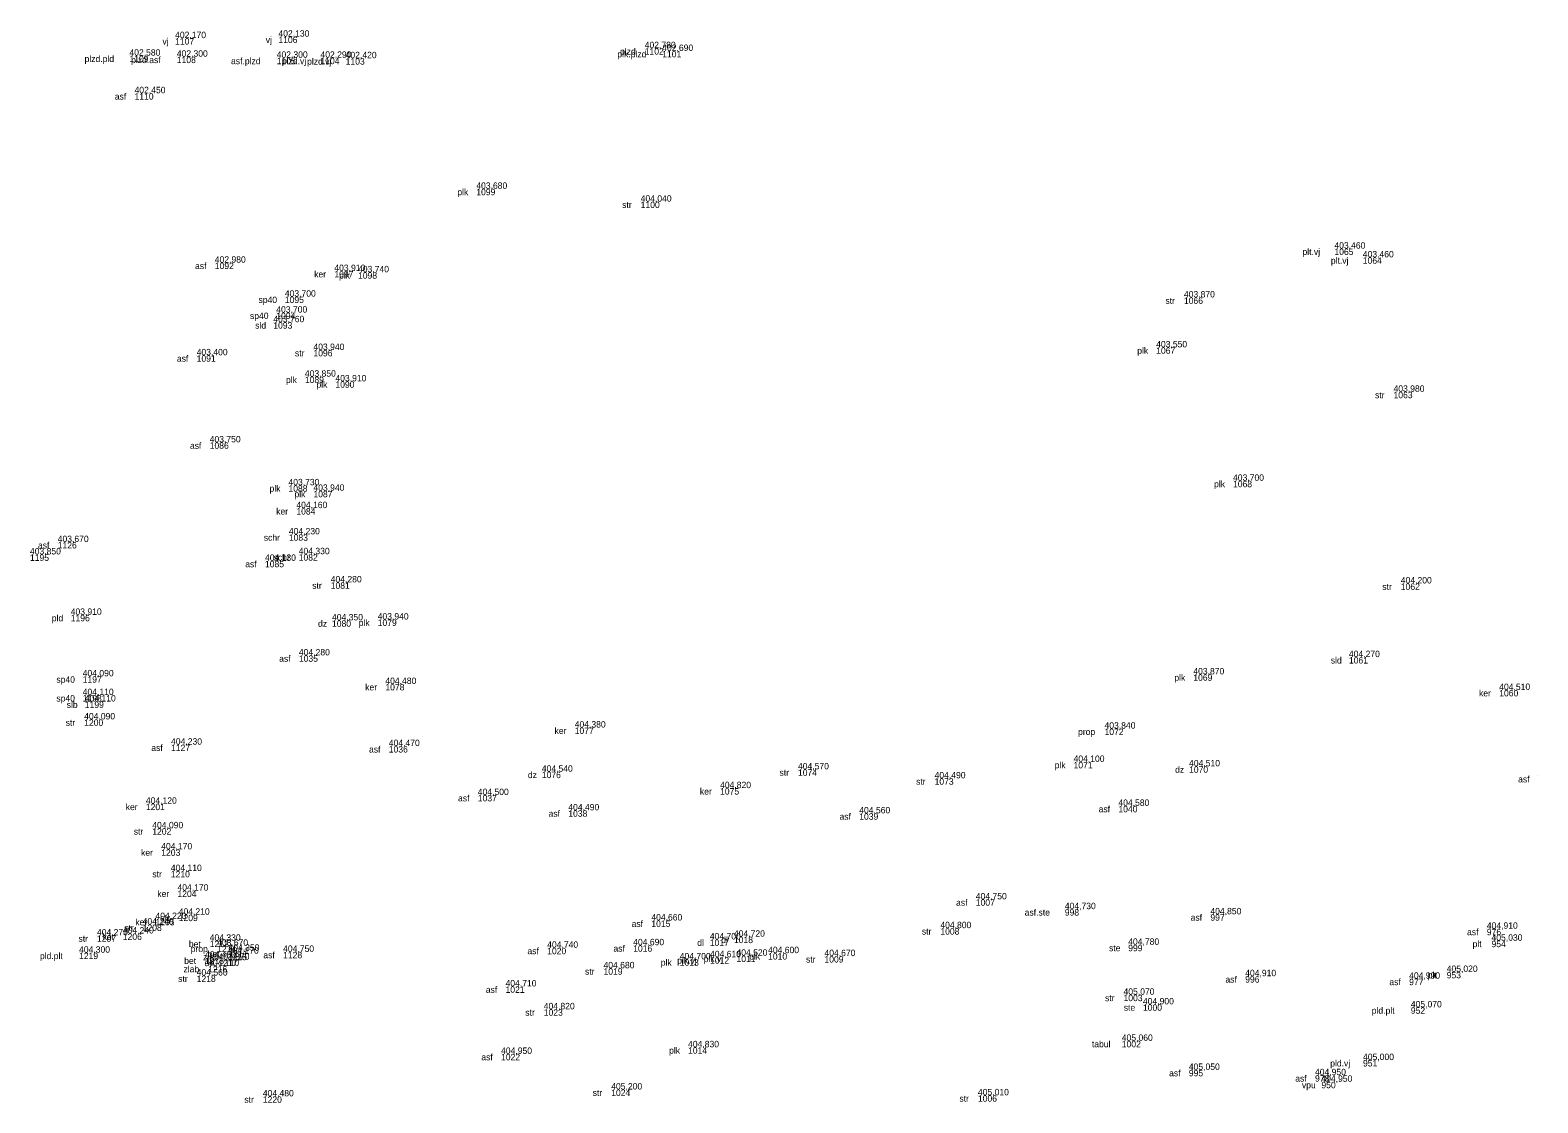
# Model space of a CAD drawing. Extents: x -747136 to -746138, y -1093274 to -1091717.
# Drawn here: x -747043 to -746972.4, y -1092170.4 to -1092120.2 of the extents above; entities that cross this region are included whole.
import ezdxf

# ---------------------------------------------------------------- set-up
doc = ezdxf.new("R2010")
doc.units = 0
for name, color, linetype in [('1029', 7, 'Continuous'), ('404', 7, 'Continuous'), ('424', 7, 'Continuous')]:
    doc.layers.add(name, color=color, linetype=linetype)

msp = doc.modelspace()

# ---------------------------------------------------------------- linework, layer by layer
at = {"layer": '404'}
for p, q in [((-747036.23, -1092120.54), (-747036.23, -1092120.54)), ((-747031.39, -1092120.47), (-747031.39, -1092120.47)), ((-747038.37, -1092121.36), (-747038.37, -1092121.36)), ((-747036.15, -1092121.41), (-747036.15, -1092121.41)), ((-747031.47, -1092121.46), (-747031.47, -1092121.46)), ((-747029.42, -1092121.46), (-747029.42, -1092121.46)), ((-747028.24, -1092121.48), (-747028.24, -1092121.48)), ((-747014.23, -1092121.01), (-747014.23, -1092121.01)), ((-747013.41, -1092121.14), (-747013.41, -1092121.14)), ((-747038.13, -1092123.12), (-747038.13, -1092123.12)), ((-747022.12, -1092127.6), (-747022.12, -1092127.6)), ((-747014.42, -1092128.2), (-747014.42, -1092128.2)), ((-746981.92, -1092130.4), (-746981.92, -1092130.4)), ((-747034.37, -1092131.06), (-747034.37, -1092131.06)), ((-747028.77, -1092131.45), (-747028.77, -1092131.45)), ((-746980.59, -1092130.81), (-746980.59, -1092130.81)), ((-747027.66, -1092131.51), (-747027.66, -1092131.51)), ((-747031.09, -1092132.65), (-747031.09, -1092132.65)), ((-746988.97, -1092132.69), (-746988.97, -1092132.69)), ((-747031.49, -1092133.4), (-747031.49, -1092133.4)), ((-747031.63, -1092133.85), (-747031.63, -1092133.85)), ((-747035.22, -1092135.4), (-747035.22, -1092135.4)), ((-747029.75, -1092135.15), (-747029.75, -1092135.15)), ((-746990.27, -1092135.03), (-746990.27, -1092135.03)), ((-747030.15, -1092136.4), (-747030.15, -1092136.4)), ((-747028.72, -1092136.62), (-747028.72, -1092136.62)), ((-746979.15, -1092137.11), (-746979.15, -1092137.11)), ((-747034.61, -1092139.48), (-747034.61, -1092139.48)), ((-746986.67, -1092141.28), (-746986.67, -1092141.28)), ((-747030.92, -1092141.49), (-747030.92, -1092141.49)), ((-747029.75, -1092141.75), (-747029.75, -1092141.75)), ((-747030.55, -1092142.56), (-747030.55, -1092142.56)), ((-747041.73, -1092144.15), (-747041.73, -1092144.15)), ((-747030.9, -1092143.79), (-747030.9, -1092143.79)), ((-747030.44, -1092144.72), (-747030.44, -1092144.72)), ((-747032.02, -1092145.03), (-747032.02, -1092145.03)), ((-747028.94, -1092146.04), (-747028.94, -1092146.04)), ((-746978.81, -1092146.09), (-746978.81, -1092146.09)), ((-747041.12, -1092147.56), (-747041.12, -1092147.56)), ((-747028.88, -1092147.82), (-747028.88, -1092147.82)), ((-747026.74, -1092147.78), (-747026.74, -1092147.78)), ((-747030.43, -1092149.46), (-747030.43, -1092149.46)), ((-746981.24, -1092149.54), (-746981.24, -1092149.54)), ((-747040.56, -1092150.44), (-747040.56, -1092150.44)), ((-746988.53, -1092150.35), (-746988.53, -1092150.35)), ((-747026.38, -1092150.8), (-747026.38, -1092150.8)), ((-746974.2, -1092151.08), (-746974.2, -1092151.08)), ((-747040.56, -1092151.32), (-747040.56, -1092151.32)), ((-747040.46, -1092151.62), (-747040.46, -1092151.62)), ((-747040.49, -1092152.46), (-747040.49, -1092152.46)), ((-747017.51, -1092152.84), (-747017.51, -1092152.84)), ((-746992.69, -1092152.89), (-746992.69, -1092152.89)), ((-747036.42, -1092153.64), (-747036.42, -1092153.64)), ((-747026.22, -1092153.71), (-747026.22, -1092153.71)), ((-746994.14, -1092154.45), (-746994.14, -1092154.45)), ((-746988.73, -1092154.66), (-746988.73, -1092154.66)), ((-747019.05, -1092154.91), (-747019.05, -1092154.91)), ((-747007.05, -1092154.8), (-747007.05, -1092154.8)), ((-747000.65, -1092155.22), (-747000.65, -1092155.22)), ((-746972.39, -1092155.11), (-746972.39, -1092155.11)), ((-747022.05, -1092156), (-747022.05, -1092156)), ((-747010.7, -1092155.68), (-747010.7, -1092155.68)), ((-747037.6, -1092156.41), (-747037.6, -1092156.41)), ((-747017.81, -1092156.72), (-747017.81, -1092156.72)), ((-747004.18, -1092156.86), (-747004.18, -1092156.86)), ((-746992.04, -1092156.51), (-746992.04, -1092156.51)), ((-747037.3, -1092157.56), (-747037.3, -1092157.56)), ((-747036.88, -1092158.55), (-747036.88, -1092158.55)), ((-747036.43, -1092159.56), (-747036.43, -1092159.56)), ((-747036.12, -1092160.48), (-747036.12, -1092160.48)), ((-746998.72, -1092160.89), (-746998.72, -1092160.89)), ((-747037.15, -1092161.81), (-747037.15, -1092161.81)), ((-747036.06, -1092161.61), (-747036.06, -1092161.61)), ((-746994.55, -1092161.35), (-746994.55, -1092161.35)), ((-746987.73, -1092161.59), (-746987.73, -1092161.59)), ((-747038.68, -1092162.49), (-747038.68, -1092162.49)), ((-747037.75, -1092162.07), (-747037.75, -1092162.07)), ((-747013.92, -1092161.88), (-747013.92, -1092161.88)), ((-747000.38, -1092162.24), (-747000.38, -1092162.24)), ((-746974.78, -1092162.27), (-746974.78, -1092162.27)), ((-747039.89, -1092162.58), (-747039.89, -1092162.58)), ((-747034.61, -1092162.83), (-747034.61, -1092162.83)), ((-747034.26, -1092163.06), (-747034.26, -1092163.06)), ((-747018.8, -1092163.16), (-747018.8, -1092163.16)), ((-747014.77, -1092163.04), (-747014.77, -1092163.04)), ((-747011.18, -1092162.77), (-747011.18, -1092162.77)), ((-747010.05, -1092162.64), (-747010.05, -1092162.64)), ((-746991.58, -1092163.02), (-746991.58, -1092163.02)), ((-746974.56, -1092162.83), (-746974.56, -1092162.83)), ((-747040.73, -1092163.39), (-747040.73, -1092163.39)), ((-747034.83, -1092163.62), (-747034.83, -1092163.62)), ((-747034.2, -1092163.72), (-747034.2, -1092163.72)), ((-747033.76, -1092163.44), (-747033.76, -1092163.44)), ((-747033.73, -1092163.3), (-747033.73, -1092163.3)), ((-747031.17, -1092163.35), (-747031.17, -1092163.35)), ((-747012.59, -1092163.7), (-747012.59, -1092163.7)), ((-747011.17, -1092163.6), (-747011.17, -1092163.6)), ((-747009.93, -1092163.53), (-747009.93, -1092163.53)), ((-747008.45, -1092163.41), (-747008.45, -1092163.41)), ((-747005.81, -1092163.55), (-747005.81, -1092163.55)), ((-747035.22, -1092164.46), (-747035.22, -1092164.46)), ((-747034.68, -1092164.01), (-747034.68, -1092164.01)), ((-747016.16, -1092164.12), (-747016.16, -1092164.12)), ((-746986.1, -1092164.49), (-746986.1, -1092164.49)), ((-746978.42, -1092164.61), (-746978.42, -1092164.61)), ((-746976.66, -1092164.29), (-746976.66, -1092164.29)), ((-747020.75, -1092164.97), (-747020.75, -1092164.97)), ((-746991.8, -1092165.36), (-746991.8, -1092165.36)), ((-747018.96, -1092166.04), (-747018.96, -1092166.04)), ((-746990.89, -1092165.81), (-746990.89, -1092165.81)), ((-746978.34, -1092165.95), (-746978.34, -1092165.95)), ((-747020.96, -1092168.13), (-747020.96, -1092168.13)), ((-747012.2, -1092167.82), (-747012.2, -1092167.82)), ((-746991.88, -1092167.52), (-746991.88, -1092167.52)), ((-746988.74, -1092168.88), (-746988.74, -1092168.88)), ((-746980.58, -1092168.42), (-746980.58, -1092168.42)), ((-746982.83, -1092169.13), (-746982.83, -1092169.13)), ((-746982.53, -1092169.44), (-746982.53, -1092169.44)), ((-747032.12, -1092170.12), (-747032.12, -1092170.12)), ((-747015.8, -1092169.8), (-747015.8, -1092169.8)), ((-746998.62, -1092170.07), (-746998.62, -1092170.07))]:
    msp.add_line(p, q, dxfattribs=at)

# ---------------------------------------------------------------- texts
at = {"layer": '1029'}
for s, p in [('402,130', (-747031.39, -1092120.47)), ('402,170', (-747036.23, -1092120.54)), ('402,780', (-747014.23, -1092121.01)), ('402,690', (-747013.41, -1092121.14)), ('402,580', (-747038.37, -1092121.36)), ('402,300', (-747036.15, -1092121.41)), ('402,300', (-747031.47, -1092121.46)), ('402,290', (-747029.42, -1092121.46)), ('402,420', (-747028.24, -1092121.48)), ('402,450', (-747038.13, -1092123.12)), ('403,680', (-747022.12, -1092127.6)), ('404,040', (-747014.42, -1092128.2)), ('402,980', (-747034.37, -1092131.06)), ('403,460', (-746981.92, -1092130.4)), ('403,460', (-746980.59, -1092130.81)), ('403,910', (-747028.77, -1092131.45)), ('403,740', (-747027.66, -1092131.51)), ('403,700', (-747031.09, -1092132.65)), ('403,870', (-746988.97, -1092132.69)), ('403,760', (-747031.63, -1092133.85)), ('403,700', (-747031.49, -1092133.4)), ('403,940', (-747029.75, -1092135.15)), ('403,550', (-746990.27, -1092135.03)), ('403,400', (-747035.22, -1092135.4)), ('403,850', (-747030.15, -1092136.4)), ('403,910', (-747028.72, -1092136.62)), ('403,980', (-746979.15, -1092137.11)), ('403,750', (-747034.61, -1092139.48)), ('403,730', (-747030.92, -1092141.49)), ('403,700', (-746986.67, -1092141.28)), ('403,940', (-747029.75, -1092141.75)), ('404,160', (-747030.55, -1092142.56)), ('403,670', (-747041.73, -1092144.15)), ('404,230', (-747030.9, -1092143.79)), ('403,850', (-747043.03, -1092144.73)), ('404,130', (-747032.02, -1092145.03)), ('404,330', (-747030.44, -1092144.72)), ('404,280', (-747028.94, -1092146.04)), ('404,200', (-746978.81, -1092146.09)), ('403,910', (-747041.12, -1092147.56)), ('404,350', (-747028.88, -1092147.82)), ('403,940', (-747026.74, -1092147.78)), ('404,280', (-747030.43, -1092149.46)), ('404,270', (-746981.24, -1092149.54)), ('404,090', (-747040.56, -1092150.44)), ('404,480', (-747026.38, -1092150.8)), ('403,870', (-746988.53, -1092150.35)), ('404,110', (-747040.56, -1092151.32)), ('404,510', (-746974.2, -1092151.08)), ('404,110', (-747040.46, -1092151.62)), ('404,090', (-747040.49, -1092152.46)), ('404,380', (-747017.51, -1092152.84)), ('403,840', (-746992.69, -1092152.89)), ('404,230', (-747036.42, -1092153.64)), ('404,470', (-747026.22, -1092153.71)), ('404,540', (-747019.05, -1092154.91)), ('404,570', (-747007.05, -1092154.8)), ('404,100', (-746994.14, -1092154.45)), ('404,510', (-746988.73, -1092154.66)), ('404,820', (-747010.7, -1092155.68)), ('404,490', (-747000.65, -1092155.22)), ('404,120', (-747037.6, -1092156.41)), ('404,500', (-747022.05, -1092156)), ('404,490', (-747017.81, -1092156.72)), ('404,560', (-747004.18, -1092156.86)), ('404,580', (-746992.04, -1092156.51)), ('404,090', (-747037.3, -1092157.56)), ('404,170', (-747036.88, -1092158.55)), ('404,110', (-747036.43, -1092159.56)), ('404,170', (-747036.12, -1092160.48)), ('404,750', (-746998.72, -1092160.89)), ('404,730', (-746994.55, -1092161.35)), ('404,240', (-747037.75, -1092162.07)), ('404,220', (-747037.15, -1092161.81)), ('404,210', (-747036.06, -1092161.61)), ('404,660', (-747013.92, -1092161.88)), ('404,850', (-746987.73, -1092161.59)), ('404,270', (-747039.89, -1092162.58)), ('404,240', (-747038.68, -1092162.49)), ('404,330', (-747034.61, -1092162.83)), ('404,700', (-747011.18, -1092162.77)), ('404,720', (-747010.05, -1092162.64)), ('404,800', (-747000.38, -1092162.24)), ('404,910', (-746974.78, -1092162.27)), ('405,030', (-746974.56, -1092162.83)), ('404,300', (-747040.73, -1092163.39)), ('403,670', (-747034.26, -1092163.06)), ('404,170', (-747033.76, -1092163.44)), ('404,350', (-747033.73, -1092163.3)), ('404,750', (-747031.17, -1092163.35)), ('404,740', (-747018.8, -1092163.16)), ('404,690', (-747014.77, -1092163.04)), ('404,520', (-747009.93, -1092163.53)), ('404,600', (-747008.45, -1092163.41)), ('404,670', (-747005.81, -1092163.55)), ('404,780', (-746991.58, -1092163.02)), ('404,460', (-747034.83, -1092163.62)), ('404,110', (-747034.68, -1092164.01)), ('403,870', (-747034.2, -1092163.72)), ('404,680', (-747016.16, -1092164.12)), ('404,700', (-747012.59, -1092163.7)), ('404,610', (-747011.17, -1092163.6)), ('404,560', (-747035.22, -1092164.46)), ('404,710', (-747020.75, -1092164.97)), ('404,910', (-746986.1, -1092164.49)), ('404,990', (-746978.42, -1092164.61)), ('405,020', (-746976.66, -1092164.29)), ('405,070', (-746991.8, -1092165.36)), ('404,820', (-747018.96, -1092166.04)), ('404,900', (-746990.89, -1092165.81)), ('405,070', (-746978.34, -1092165.95)), ('405,060', (-746991.88, -1092167.52)), ('404,950', (-747020.96, -1092168.13)), ('404,830', (-747012.2, -1092167.82)), ('405,000', (-746980.58, -1092168.42)), ('405,050', (-746988.74, -1092168.88)), ('404,950', (-746982.83, -1092169.13)), ('405,200', (-747015.8, -1092169.8)), ('404,950', (-746982.53, -1092169.44)), ('404,480', (-747032.12, -1092170.12)), ('405,010', (-746998.62, -1092170.07))]:
    msp.add_text(s, height=0.3, dxfattribs=at).set_placement(p)
at = {"layer": '424'}
for s, p in [(' vj', (-747036.934, -1092120.84)), ('1107', (-747036.23, -1092120.84)), (' vj', (-747032.094, -1092120.77)), ('1106', (-747031.39, -1092120.77)), (' plzd.pld', (-747040.583, -1092121.66)), ('1109', (-747038.37, -1092121.66)), (' plzd.asf', (-747038.401, -1092121.71)), ('1108', (-747036.15, -1092121.71)), (' asf.plzd', (-747033.721, -1092121.76)), ('1105', (-747031.47, -1092121.76)), (' plzd.vj', (-747031.338, -1092121.76)), (' plzd.vj', (-747030.158, -1092121.78)), ('1104', (-747029.42, -1092121.76)), ('1103', (-747028.24, -1092121.78)), (' plk.plzd', (-747015.623, -1092121.44)), (' plzd', (-747015.498, -1092121.31)), ('1102', (-747014.23, -1092121.31)), ('1101', (-747013.41, -1092121.44)), (' asf', (-747039.167, -1092123.42)), ('1110', (-747038.13, -1092123.42)), (' plk', (-747023.119, -1092127.9)), ('1099', (-747022.12, -1092127.9)), (' str', (-747015.398, -1092128.5)), ('1100', (-747014.42, -1092128.5)), (' plt.vj', (-746983.528, -1092130.7)), ('1065', (-746981.92, -1092130.7)), (' asf', (-747035.407, -1092131.36)), ('1092', (-747034.37, -1092131.36)), (' ker', (-747029.826, -1092131.75)), ('1097', (-747028.77, -1092131.75)), (' plt.vj', (-746982.198, -1092131.11)), ('1064', (-746980.59, -1092131.11)), (' plk', (-747028.659, -1092131.81)), ('1098', (-747027.66, -1092131.81)), (' sp40', (-747032.434, -1092132.95)), ('1095', (-747031.09, -1092132.95)), (' str', (-746989.948, -1092132.99)), ('1066', (-746988.97, -1092132.99)), (' sp40', (-747032.834, -1092133.7)), ('1094', (-747031.49, -1092133.7)), (' sld', (-747032.591, -1092134.15)), ('1093', (-747031.63, -1092134.15)), (' asf', (-747036.257, -1092135.7)), ('1091', (-747035.22, -1092135.7)), (' str', (-747030.728, -1092135.45)), ('1096', (-747029.75, -1092135.45)), (' plk', (-746991.269, -1092135.33)), ('1067', (-746990.27, -1092135.33)), (' plk', (-747031.149, -1092136.7)), ('1089', (-747030.15, -1092136.7)), (' plk', (-747029.719, -1092136.92)), ('1090', (-747028.72, -1092136.92)), ('1063', (-746979.15, -1092137.41)), (' str', (-746980.128, -1092137.41)), (' asf', (-747035.647, -1092139.78)), ('1086', (-747034.61, -1092139.78)), (' plk', (-746987.669, -1092141.58)), ('1068', (-746986.67, -1092141.58)), (' plk', (-747031.919, -1092141.79)), ('1088', (-747030.92, -1092141.79)), (' plk', (-747030.749, -1092142.05)), ('1087', (-747029.75, -1092142.05)), (' ker', (-747031.606, -1092142.86)), ('1084', (-747030.55, -1092142.86)), (' asf', (-747042.767, -1092144.45)), ('1126', (-747041.73, -1092144.45)), (' schr', (-747032.187, -1092144.09)), ('1083', (-747030.9, -1092144.09)), ('1195', (-747043.03, -1092145.03)), (' schr', (-747031.727, -1092145.02)), ('1082', (-747030.44, -1092145.02)), (' asf', (-747033.057, -1092145.33)), ('1085', (-747032.02, -1092145.33)), (' str', (-747029.918, -1092146.34)), ('1081', (-747028.94, -1092146.34)), (' str', (-746979.788, -1092146.39)), ('1062', (-746978.81, -1092146.39)), (' pld', (-747042.119, -1092147.86)), ('1196', (-747041.12, -1092147.86)), (' dz', (-747029.645, -1092148.12)), ('1080', (-747028.88, -1092148.12)), (' plk', (-747027.739, -1092148.08)), ('1079', (-747026.74, -1092148.08)), (' asf', (-747031.467, -1092149.76)), ('1035', (-747030.43, -1092149.76)), (' sld', (-746982.201, -1092149.84)), ('1061', (-746981.24, -1092149.84)), (' sp40', (-747041.904, -1092150.74)), ('1197', (-747040.56, -1092150.74)), (' plk', (-746989.529, -1092150.65)), ('1069', (-746988.53, -1092150.65)), (' ker', (-747027.436, -1092151.1)), ('1078', (-747026.38, -1092151.1)), (' ker', (-746975.256, -1092151.38)), ('1060', (-746974.2, -1092151.38)), (' sp40', (-747041.904, -1092151.62)), (' slb', (-747041.421, -1092151.92)), ('1198', (-747040.56, -1092151.62)), ('1199', (-747040.46, -1092151.92)), (' str', (-747041.468, -1092152.76)), ('1200', (-747040.49, -1092152.76)), (' ker', (-747018.566, -1092153.14)), ('1077', (-747017.51, -1092153.14)), (' prop', (-746994.041, -1092153.19)), ('1072', (-746992.69, -1092153.19)), (' asf', (-747037.457, -1092153.94)), ('1127', (-747036.42, -1092153.94)), (' asf', (-747027.257, -1092154.01)), ('1036', (-747026.22, -1092154.01)), (' plk', (-746995.139, -1092154.75)), ('1071', (-746994.14, -1092154.75)), (' dz', (-746989.495, -1092154.96)), ('1070', (-746988.73, -1092154.96)), (' dz', (-747019.815, -1092155.21)), ('1076', (-747019.05, -1092155.21)), (' str', (-747008.028, -1092155.1)), ('1074', (-747007.05, -1092155.1)), (' str', (-747001.628, -1092155.52)), ('1073', (-747000.65, -1092155.52)), (' asf', (-746973.427, -1092155.41)), (' asf', (-747023.087, -1092156.3)), ('1037', (-747022.05, -1092156.3)), (' ker', (-747011.756, -1092155.98)), ('1075', (-747010.7, -1092155.98)), (' ker', (-747038.656, -1092156.71)), ('1201', (-747037.6, -1092156.71)), (' asf', (-747018.847, -1092157.02)), ('1038', (-747017.81, -1092157.02)), (' asf', (-747005.217, -1092157.16)), ('1039', (-747004.18, -1092157.16)), (' asf', (-746993.077, -1092156.81)), ('1040', (-746992.04, -1092156.81)), (' str', (-747038.278, -1092157.86)), ('1202', (-747037.3, -1092157.86)), (' ker', (-747037.936, -1092158.85)), ('1203', (-747036.88, -1092158.85)), (' str', (-747037.408, -1092159.86)), ('1210', (-747036.43, -1092159.86)), (' ker', (-747037.176, -1092160.78)), ('1204', (-747036.12, -1092160.78)), (' asf', (-746999.757, -1092161.19)), ('1007', (-746998.72, -1092161.19)), (' ker', (-747038.206, -1092162.11)), ('1205', (-747037.15, -1092162.11)), (' str', (-747037.038, -1092161.91)), ('1209', (-747036.06, -1092161.91)), (' asf.ste', (-746996.541, -1092161.65)), ('998', (-746994.55, -1092161.65)), (' asf', (-746988.767, -1092161.89)), ('997', (-746987.73, -1092161.89)), (' ker', (-747039.736, -1092162.79)), ('1206', (-747038.68, -1092162.79)), (' str', (-747038.728, -1092162.37)), ('1208', (-747037.75, -1092162.37)), (' asf', (-747014.957, -1092162.18)), ('1015', (-747013.92, -1092162.18)), (' str', (-747001.358, -1092162.54)), ('1008', (-747000.38, -1092162.54)), (' asf', (-746975.817, -1092162.57)), ('976', (-746974.78, -1092162.57)), (' str', (-747040.868, -1092162.88)), ('1207', (-747039.89, -1092162.88)), (' bet', (-747035.696, -1092163.13)), (' prop', (-747035.611, -1092163.36)), ('1212', (-747034.61, -1092163.13)), ('1214', (-747034.26, -1092163.36)), (' asf', (-747019.837, -1092163.46)), ('1020', (-747018.8, -1092163.46)), (' asf', (-747015.807, -1092163.34)), ('1016', (-747014.77, -1092163.34)), (' dl', (-747011.884, -1092163.07)), ('1017', (-747011.18, -1092163.07)), (' dl', (-747010.754, -1092162.94)), ('1018', (-747010.05, -1092162.94)), (' ste', (-746992.589, -1092163.32)), ('999', (-746991.58, -1092163.32)), (' plt', (-746975.559, -1092163.13)), ('954', (-746974.56, -1092163.13)), (' pld.plt', (-747042.674, -1092163.69)), ('1219', (-747040.73, -1092163.69)), (' bet', (-747035.916, -1092163.92)), (' zlab', (-747035.028, -1092163.74)), (' dh', (-747034.965, -1092164.02)), ('1213', (-747034.83, -1092163.92)), (' bet', (-747034.816, -1092163.6)), ('1217', (-747034.2, -1092164.02)), ('1215', (-747033.76, -1092163.74)), ('1211', (-747033.73, -1092163.6)), (' asf', (-747032.207, -1092163.65)), ('1128', (-747031.17, -1092163.65)), (' plk', (-747013.589, -1092164)), (' plk.vj', (-747012.819, -1092163.9)), ('1013', (-747012.59, -1092164)), (' plk.vj', (-747011.579, -1092163.83)), ('1012', (-747011.17, -1092163.9)), ('1011', (-747009.93, -1092163.83)), (' plk', (-747009.449, -1092163.71)), ('1010', (-747008.45, -1092163.71)), (' str', (-747006.788, -1092163.85)), ('1009', (-747005.81, -1092163.85)), (' str', (-747036.198, -1092164.76)), (' zlab', (-747035.948, -1092164.31)), ('1218', (-747035.22, -1092164.76)), ('1216', (-747034.68, -1092164.31)), (' str', (-747017.138, -1092164.42)), ('1019', (-747016.16, -1092164.42)), (' asf', (-746987.137, -1092164.79)), ('996', (-746986.1, -1092164.79)), (' asf', (-746979.457, -1092164.91)), ('977', (-746978.42, -1092164.91)), (' plt', (-746977.659, -1092164.59)), ('953', (-746976.66, -1092164.59)), (' asf', (-747021.787, -1092165.27)), ('1021', (-747020.75, -1092165.27)), ('1003', (-746991.8, -1092165.66)), (' str', (-747019.938, -1092166.34)), ('1023', (-747018.96, -1092166.34)), (' str', (-746992.778, -1092165.66)), (' ste', (-746991.899, -1092166.11)), ('1000', (-746990.89, -1092166.11)), (' pld.plt', (-746980.284, -1092166.25)), ('952', (-746978.34, -1092166.25)), (' asf', (-747021.997, -1092168.43)), ('1022', (-747020.96, -1092168.43)), (' plk', (-747013.199, -1092168.12)), ('1014', (-747012.2, -1092168.12)), (' tabul', (-746993.392, -1092167.82)), ('1002', (-746991.88, -1092167.82)), (' asf', (-746989.777, -1092169.18)), ('995', (-746988.74, -1092169.18)), (' pld.vj', (-746982.229, -1092168.72)), ('951', (-746980.58, -1092168.72)), (' asf', (-746983.867, -1092169.43)), (' vpu', (-746983.553, -1092169.74)), ('978', (-746982.83, -1092169.43)), ('950', (-746982.53, -1092169.74)), (' str', (-747033.098, -1092170.42)), ('1220', (-747032.12, -1092170.42)), (' str', (-747016.778, -1092170.1)), ('1024', (-747015.8, -1092170.1)), (' str', (-746999.598, -1092170.37)), ('1006', (-746998.62, -1092170.37))]:
    msp.add_text(s, height=0.3, dxfattribs=at).set_placement(p)

doc.saveas('drawing.dxf')
